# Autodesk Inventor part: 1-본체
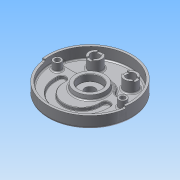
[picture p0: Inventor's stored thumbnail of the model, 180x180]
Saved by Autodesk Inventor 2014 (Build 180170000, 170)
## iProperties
Created: 2015-06
Part Number: 1-본체
Material: 알루미늄 6061
Document SubType Name: Modeling
Designer: Administrator
Density: 2.71 g/cm^3
Appearance: 알루미늄 - 평지
Mass: 1071 g
Surface Area: 1034.49 cm^2
Volume: 395.202 cm^3
Author: Administrator
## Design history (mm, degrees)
sketch "스케치1"
  geometry: C1 r 95 at (0, 0); 1 further point
  constraints: 1 centre point, 1 coincident
  dimensions: "d0" = 190 diameter of C1
extrude "돌출1" new body sketch "스케치1" distance "d1" = 32; taper "d2" = 0 deg
sketch "스케치2"
  geometry: C1 r 95 at (0, 0) reference; C2 r 90 at (0, 0)
  constraints: 1 centre point, 1 coincident
  dimensions: "d3" = 180 diameter of C2
extrude "돌출2" cut sketch "스케치2" distance "d4" = 18; taper "d5" = 0 deg
sketch "스케치3"
  geometry: L1 (-38.833, 16)-(-88.566, 16); L2 (38.833, 16)-(88.566, 16); A1 r 90 centre (0, 0) between (-88.566, 16) and (88.566, 16) reference; A2 r 42 centre (0, 0) between (38.833, 16) and (-38.833, 16)
  constraints: 4 end point, 4 point on circle, 2 collinear, 1 centre point, 1 coincident, 1 horizontal
  dimensions: "d6" = 84 diameter of A2; "d7" = 16 distance from line of A1.centre L1
extrude "돌출3" cut sketch "스케치3" distance "d8" = 7; taper "d9" = 0 deg
sketch "스케치4"
  geometry: C1 r 35 at (0, 0); A1 r 42 centre (0, 0) between (38.833, 16) and (-38.833, 16) reference
  constraints: 1 centre point, 1 coincident
  dimensions: "d10" = 70 diameter of C1
extrude "돌출4" join sketch "스케치4" distance "d11" = 10; taper "d12" = -10 deg
sketch "스케치5"
  geometry: L1 (-95, 0)-(95, 0); L2 (0, 0)-(-94.075, -13.221); L3 (0, 0)-(94.075, -13.221); C1 r 90 at (0, 0) reference; A1 r 95 centre (0, 0) between (-95, 0) and (95, 0) reference
  constraints: 6 end point, 4 point on circle, 1 coincident, 1 horizontal, 1 midpoint
  dimensions: "d13" = 8 deg angle of L1 L2; "d14" = 8 deg angle of L3 L1
extrude "돌출5" cut sketch "스케치5" distance "d15" = 5; taper "d16" = 0 deg
sketch "스케치6"
  geometry: L1 (88.566, 16)-(38.833, 16) reference; L2 (-74, 0)-(74, 0); C1 r 35 at (0, 0) reference; C2 r 9 at (-74, 0); C3 r 9 at (74, 0); 1 further point
  constraints: 3 coincident, 2 centre point, 2 end point, 1 midpoint, 1 parallel
  dimensions: "d17" = 148 distance of L2.start L2.end; "d18" = 18 diameter of C2; "d19" = 18 diameter of C3
extrude "돌출6" join sketch "스케치6" stored distance "d20" = 5; taper "d21" = 0 deg
sketch "스케치7"
  geometry: L1 (88.566, 16)-(38.833, 16) reference; L2 (-87.972, -19)-(87.972, -19); L3 (-88.904, -14)-(88.904, -14); L4 (-59, -19)-(-59, -16.477); L5 (-59, -16.477)-(-59, -14); L6 (-41, -19)-(-41, -14); L7 (41, -19)-(41, -14); L8 (59, -19)-(59, -14); C1 r 35 at (0, 0) reference; A1 r 90 centre (0, 0) between (-88.566, 16) and (88.566, 16) reference; A2 r 59 centre (0, -19) between (-59, -19) and (59, -19); A3 r 41 centre (0, -19) between (-41, -19) and (41, -19); A4 r 9 centre (-50, -14) between (-41, -14) and (-59, -14); A5 r 9 centre (50, -14) between (59, -14) and (41, -14)
  constraints: 14 end point, 12 point on circle, 8 point on line, 8 tangent, 4 centre point, 4 perpendicular, 2 parallel, 1 coincident, 1 midpoint, 1 vertical alignment
  dimensions: "d22" = 19 distance of A2.centre C1.centre; "d23" = 118 diameter of A2; "d24" = 82 diameter of A3; "d25" = 5 distance between parallel lines of L3 L2
extrude "돌출7" cut sketch "스케치7" distance "d26" = 7; taper "d27" = 0 deg
sketch "스케치8"
  geometry: L1 (-38.833, 16)-(-88.566, 16) reference; L2 (-40, 52)-(40, 52); C1 r 15 at (-40, 52); C2 r 15 at (40, 52); A1 r 42 centre (0, 0) between (38.833, 16) and (-38.833, 16) reference; 1 further point
  constraints: 2 centre point, 2 coincident, 2 end point, 1 midpoint, 1 parallel, 1 vertical alignment
  dimensions: "d28" = 52 distance of A1.centre point (0, 52); "d29" = 80 distance of L2.start L2.end; "d30" = 30 diameter of C1; "d31" = 30 diameter of C2
extrude "돌출8" join sketch "스케치8" stored distance "d32" = 7; taper "d33" = 0 deg
sketch "스케치9"
  geometry: C1 r 95 at (0, 0) reference; C2 r 26 at (0, 0)
  constraints: 1 centre point, 1 coincident
  dimensions: "d34" = 52 diameter of C2
extrude "돌출9" join sketch "스케치9" distance "d35" = 12; taper "d36" = -15 deg
hole "구멍1" diameter "d39" = 23; stored, may be unused: countersink angle "d43" = 90 deg, drill point angle "d45" = 118 deg; dims "d37" = 10, "d38" = 10, "d40" = 6, "d41" = 50, "d42" = 15, "d44" = 8
sketch "스케치10"
  geometry: C1 r 15 at (0, 0) reference; C2 r 15 at (80, 0) reference; 3 further points
  constraints: 2 coincident
hole "구멍2" sketch "스케치10" at (0, 0), (80, 0) diameter "d46" = 20; stored, may be unused: countersink angle "d50" = 90 deg, drill point angle "d52" = 118 deg; dims "d47" = 6, "d48" = 50, "d49" = 15, "d51" = 8
sketch "스케치11"
  geometry: C1 r 10 at (40, 52) reference; C2 r 10 at (-40, 52) reference; C3 r 26 at (0, 0) reference; C4 r 95 at (0, 0) reference; C5 r 9 at (-74, 0) reference; C6 r 9 at (74, 0) reference; 2 further points
  constraints: 2 coincident
hole "구멍3" sketch "스케치11" at (-74, 0), (74, 0) diameter "d53" = 11; stored, may be unused: countersink angle "d57" = 90 deg, drill point angle "d59" = 118 deg; dims "d54" = 6, "d55" = 18, "d56" = 11, "d58" = 8
sketch "스케치12"
  geometry: C1 r 95 at (0, 0) reference; C2 r 68 at (0, 0)
  constraints: 1 centre point, 1 coincident, 1 other
  dimensions: "d60" = 136 diameter of C2
feature "엠보싱1" sketch "스케치12" dims "d61" = 0.5, "d62" = 0
sketch "스케치13"
  geometry: L1 (-6, 13.748)-(-6, -13.748); L2 (6, 13.748)-(6, -13.748); L3 (66.252, 6)-(93.748, 6); L4 (66.252, -6)-(93.748, -6); C1 r 10 at (80, 0) reference; A1 r 15 centre (0, 0) between (-6, 13.748) and (-6, -13.748) reference; A2 r 15 centre (80, 0) between (66.252, 6) and (93.748, 6) reference; 1 further point
  constraints: 8 end point, 8 point on circle, 4 parallel, 1 perpendicular, 1 vertical
  dimensions: "d63" = 12 distance from line of L2.start L1; "d64" = 12 distance between parallel lines of L4 L3
extrude "돌출10" cut sketch "스케치13" distance "d65" = 3; taper "d66" = 0 deg
chamfer "모따기1" distance "d67" = 1; stored, may be unused: second distance "d68" = 2, angle "d69" = 45 deg
fillet "모깎기1" dims "d70" = 10, "d71" = 0.3, "d72" = 1, "d73" = 5
fillet "모깎기2" dims "d74" = 3
node "솔리드1"
node "투영된 루프1"
node "투영된 루프2"
node "투영된 루프3"
